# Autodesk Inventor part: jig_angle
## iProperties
Shininess: 64.0
Length Units: 11272
Angle Units: 11279
Time Units: 11290
Mass Units: 11286
Length Display Precision: 3
Angle Display Precision: 2
Compacted: True
Part Number: jig_angle
Document SubType Name: Modeling
Created: 2004-09
Designer: John Blackburn
Material: Aluminum-6061
Manufacturer: Standard
Standards Organization: Custom
Density: 0.0
Volumn: 0.0
Area: 0.0
PropertySet Name: Model Information
Control State: 0
Master: False
Checked Out: False
Author: John Blackburn
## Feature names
1. Extrusion1
2. Extrusion2
